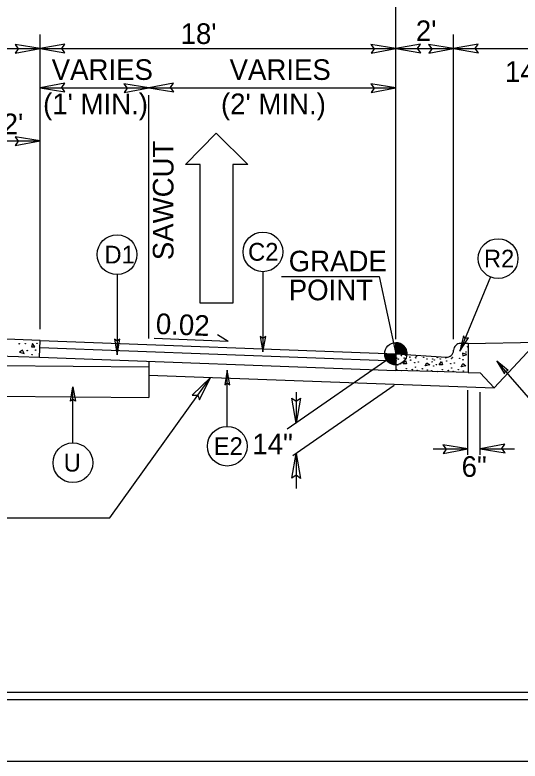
# Model space of a CAD drawing. Extents: x 573748 to 574632, y -54663 to -53209.
# Drawn here: x 574127.2 to 574163.9, y -54603.6 to -54549.4 of the extents above; entities that cross this region are included whole.
import ezdxf

# ---------------------------------------------------------------- set-up
doc = ezdxf.new("R2010")
doc.units = 0
for name, color, linetype in [('Prop Dimension', 7, 'Continuous'), ('Prop Dimension Text', 7, 'Continuous'), ('Prop Lane Arrow CELL', 7, 'Continuous'), ('Prop Terminator CELL', 7, 'Continuous'), ('Sheet Cutting Line CELL', 7, 'Continuous'), ('Sheet Plot Border Inside CELL', 7, 'Continuous'), ('Sheet Plot Border Outside CELL', 7, 'Continuous'), ('Sheet Typical CELL', 7, 'Continuous'), ('Typical Arrow Superelevation CELL', 7, 'Continuous'), ('Typical Curb CELL', 7, 'Continuous'), ('Typical Grade Point Symbol CELL', 7, 'Continuous'), ('Typical ID Circle CELL', 7, 'Continuous'), ('Typical Pavement Slope CELL', 7, 'Continuous'), ('Typical Terminator CELL', 7, 'Continuous'), ('Typical Text ID Circle CELL', 7, 'Continuous')]:
    doc.layers.add(name, color=color, linetype=linetype)

# ---------------------------------------------------------------- blocks, each defined once
blk = doc.blocks.new('Lane Arrow Through')
at = {"layer": 'Prop Lane Arrow CELL'}
for p, q in [((-3.15, 1.6), (-3.15, 3.1)), ((-3.15, 3.1), (0, 0)), ((-17.15, 1.6), (-3.15, 1.6)), ((-17.15, -1.7), (-17.15, 1.6)), ((0, 0), (-3.15, -3.2)), ((-3.15, -1.7), (-17.15, -1.7)), ((-3.15, -3.2), (-3.15, -1.7))]:
    blk.add_line(p, q, dxfattribs=at)

msp = doc.modelspace()

# ---------------------------------------------------------------- linework, layer by layer
at = {"layer": 'Prop Dimension'}
for p, q in [((574154.894, -54572.971), (574154.894, -54540.95)), ((574129.029, -54572.233), (574129.029, -54550.814)), ((574159.086, -54572.971), (574159.086, -54550.814)), ((574120.665, -54551.839), (574129.029, -54551.839)), ((574129.029, -54551.839), (574154.894, -54551.839)), ((574154.894, -54551.839), (574159.086, -54551.839)), ((574159.086, -54551.839), (574174.967, -54551.839)), ((574129.029, -54554.69), (574136.935, -54554.69)), ((574136.935, -54554.69), (574154.894, -54554.69)), ((574136.935, -54572.927), (574136.935, -54555.211)), ((574124.824, -54558.544), (574129.029, -54558.544)), ((574029.942, -54574.073), (574136.935, -54574.974)), ((574154.478, -54574.319), (574146.994, -54579.52)), ((574136.935, -54575.212), (574136.935, -54577.21)), ((574029.942, -54576.31), (574136.935, -54577.21)), ((574154.774, -54576.33), (574147.418, -54581.443)), ((574147.648, -54576.812), (574147.648, -54579.065)), ((574160.131, -54581.378), (574160.131, -54576.685)), ((574161.021, -54581.378), (574161.021, -54576.832)), ((574157.62, -54580.94), (574160.131, -54580.94)), ((574161.021, -54580.94), (574163.527, -54580.94)), ((574147.648, -54581.283), (574147.648, -54583.818))]:
    msp.add_line(p, q, dxfattribs=at)
for points in [[(574146.585, -54568.4), (574153.674, -54568.4), (574154.894, -54574.029)], [(574124.244, -54585.952), (574134.095, -54585.952), (574141.412, -54575.744)]]:
    msp.add_lwpolyline(points, dxfattribs=at)
at = {"layer": 'Prop Terminator CELL'}
for points in [[(574127.232, -54552.172), (574129.029, -54551.839), (574127.214, -54551.542), (574127.448, -54551.859)], [(574130.825, -54551.506), (574129.029, -54551.839), (574130.843, -54552.136), (574130.609, -54551.818)], [(574153.097, -54552.172), (574154.894, -54551.839), (574153.079, -54551.542), (574153.313, -54551.859)], [(574156.69, -54551.506), (574154.894, -54551.839), (574156.708, -54552.136), (574156.474, -54551.818)], [(574157.29, -54552.172), (574159.086, -54551.839), (574157.272, -54551.542), (574157.506, -54551.859)], [(574160.883, -54551.506), (574159.086, -54551.839), (574160.901, -54552.136), (574160.667, -54551.818)], [(574130.825, -54554.357), (574129.029, -54554.69), (574130.843, -54554.987), (574130.609, -54554.67)], [(574138.731, -54554.357), (574136.935, -54554.69), (574138.749, -54554.987), (574138.515, -54554.67)], [(574135.138, -54555.023), (574136.935, -54554.69), (574135.12, -54554.393), (574135.355, -54554.71)], [(574153.097, -54555.023), (574154.894, -54554.69), (574153.079, -54554.393), (574153.313, -54554.71)], [(574127.232, -54558.877), (574129.029, -54558.544), (574127.214, -54558.247), (574127.448, -54558.564)], [(574140.615, -54577.388), (574141.412, -54575.744), (574140.097, -54577.029), (574140.491, -54577.029)], [(574147.958, -54577.265), (574147.648, -54579.065), (574147.328, -54577.255), (574147.648, -54577.485)], [(574158.335, -54581.273), (574160.131, -54580.94), (574158.317, -54580.643), (574158.551, -54580.96)], [(574162.818, -54580.607), (574161.021, -54580.94), (574162.836, -54581.237), (574162.602, -54580.92)], [(574147.338, -54583.084), (574147.648, -54581.283), (574147.968, -54583.094), (574147.648, -54582.864)]]:
    msp.add_lwpolyline(points, close=True, dxfattribs=at)
at = {"layer": 'Sheet Cutting Line CELL'}
msp.add_line((573944.171, -54603.647), (574280.971, -54603.647), dxfattribs=at)
at = {"layer": 'Sheet Plot Border Inside CELL'}
msp.add_lwpolyline([(574280.071, -54388.137), (573946.771, -54388.137), (573946.771, -54599.157), (574280.071, -54599.157)], close=True, dxfattribs=at)
at = {"layer": 'Sheet Plot Border Outside CELL'}
msp.add_lwpolyline([(574280.971, -54383.647), (573944.171, -54383.647), (573944.171, -54603.647), (574280.971, -54603.647)], close=True, dxfattribs=at)
at = {"layer": 'Sheet Typical CELL'}
msp.add_lwpolyline([(574277.571, -54388.647), (573977.571, -54388.647), (573977.571, -54598.647), (574277.571, -54598.647)], close=True, dxfattribs=at)
at = {"layer": 'Typical Arrow Superelevation CELL'}
for q in [(574141.936, -54572.652), (574137.319, -54572.918)]:
    msp.add_line((574142.709, -54573.142), q, dxfattribs=at)
at = {"layer": 'Typical Curb CELL'}
for p, q in [((574129.029, -54573.062), (574124.824, -54572.904)), ((574128.484, -54573.276), (574128.403, -54573.512)), ((574128.656, -54573.535), (574128.484, -54573.276)), ((574128.984, -54574.286), (574129.029, -54573.062)), ((574160.154, -54573.292), (574159.608, -54573.278)), ((574127.762, -54573.762), (574127.54, -54573.911)), ((574127.884, -54574.007), (574127.762, -54573.762)), ((574128.403, -54573.512), (574128.656, -54573.535)), ((574159.093, -54573.789), (574159.093, -54573.766)), ((574120.588, -54573.979), (574128.984, -54574.286)), ((574127.54, -54573.911), (574127.884, -54574.007)), ((574154.894, -54574.029), (574158.557, -54574.277)), ((574159.736, -54573.98), (574159.766, -54574.17)), ((574160.057, -54574.082), (574159.736, -54573.98)), ((574159.766, -54574.17), (574160.057, -54574.082)), ((574155.421, -54574.763), (574155.608, -54574.517)), ((574155.674, -54574.757), (574155.421, -54574.763)), ((574155.608, -54574.517), (574155.674, -54574.757)), ((574157.022, -54574.912), (574157.159, -54574.675)), ((574157.371, -54574.838), (574157.022, -54574.912)), ((574157.159, -54574.675), (574157.371, -54574.838)), ((574158.039, -54574.831), (574158.225, -54574.585)), ((574158.291, -54574.825), (574158.039, -54574.831)), ((574158.225, -54574.585), (574158.291, -54574.825)), ((574159.638, -54574.979), (574159.776, -54574.743)), ((574159.987, -54574.906), (574159.638, -54574.979)), ((574159.776, -54574.743), (574159.987, -54574.906)), ((574160.154, -54575.388), (574154.894, -54575.252))]:
    msp.add_line(p, q, dxfattribs=at)
for centre in [(574127.516, -54573.302), (574127.964, -54573.298), (574128.811, -54573.268), (574128.099, -54573.793), (574128.712, -54573.764), (574159.667, -54573.438), (574160.002, -54573.901), (574160.12, -54573.522), (574128.455, -54574.091), (574154.956, -54574.344), (574155.072, -54574.418), (574155.306, -54574.163), (574155.504, -54574.346), (574155.606, -54574.135), (574155.913, -54574.275), (574156.343, -54574.319), (574156.381, -54574.215), (574156.918, -54574.288), (574157.167, -54574.401), (574157.573, -54574.411), (574157.921, -54574.295), (574158.121, -54574.414), (574158.531, -54574.342), (574158.96, -54574.387), (574158.999, -54574.282), (574159.535, -54574.356), (574154.915, -54574.546), (574155.027, -54574.848), (574155.231, -54574.758), (574155.968, -54574.489), (574156.274, -54574.677), (574156.539, -54574.624), (574157.532, -54574.614), (574157.644, -54574.916), (574157.689, -54574.486), (574157.848, -54574.825), (574158.585, -54574.557), (574158.891, -54574.745), (574159.156, -54574.692), (574159.784, -54574.468), (574154.948, -54575.181), (574155.326, -54575.251), (574155.664, -54575.116), (574156.093, -54575.175), (574156.337, -54575.002), (574156.451, -54575.244), (574156.825, -54575.122), (574157.181, -54575.215), (574157.503, -54575.259), (574157.943, -54575.318), (574158.281, -54575.184), (574158.71, -54575.243), (574158.954, -54575.069), (574159.068, -54575.312), (574159.442, -54575.19), (574159.799, -54575.283)]:
    msp.add_circle(centre, 0.0168, dxfattribs=at)
for centre, start, end in [((574159.595, -54573.779), 88.5196, 178.5196), ((574158.591, -54573.776), 266.1351, 358.5196)]:
    msp.add_arc(centre, 0.502, start, end, dxfattribs=at)
at = {"layer": 'Typical Grade Point Symbol CELL'}
for p, q in [((574154.894, -54574.029), (574154.894, -54573.224)), ((574154.088, -54574.029), (574154.894, -54574.029)), ((574154.892, -54574.835), (574154.894, -54574.029)), ((574154.894, -54574.029), (574154.892, -54574.835)), ((574155.699, -54574.029), (574154.894, -54574.029))]:
    msp.add_line(p, q, dxfattribs=at)
for points in [[(574154.901, -54573.224), (574154.901, -54573.224), (574154.901, -54574.029)], [(574154.917, -54573.224), (574154.917, -54574.029)], [(574154.933, -54573.225), (574154.933, -54574.029)], [(574154.949, -54573.225), (574154.949, -54574.029)], [(574154.965, -54573.227), (574154.965, -54574.029)], [(574154.981, -54573.229), (574154.981, -54574.029)], [(574154.998, -54573.231), (574154.998, -54574.029)], [(574155.014, -54573.232), (574155.014, -54574.029)], [(574155.03, -54573.234), (574155.03, -54574.029)], [(574155.046, -54573.238), (574155.046, -54574.029)], [(574155.062, -54573.241), (574155.062, -54574.029)], [(574155.078, -54573.245), (574155.078, -54574.029)], [(574155.094, -54573.249), (574155.094, -54574.029)], [(574155.11, -54573.254), (574155.11, -54574.029)], [(574155.126, -54573.258), (574155.126, -54574.029)], [(574155.143, -54573.263), (574155.143, -54574.029)], [(574155.159, -54573.268), (574155.159, -54574.029)], [(574155.175, -54573.274), (574155.175, -54574.029)], [(574155.191, -54573.281), (574155.191, -54574.029)], [(574155.207, -54573.288), (574155.207, -54574.029)], [(574155.223, -54573.295), (574155.223, -54574.029)], [(574155.239, -54573.302), (574155.239, -54574.029)], [(574155.255, -54573.309), (574155.255, -54574.029)], [(574155.272, -54573.318), (574155.272, -54574.029)], [(574155.288, -54573.327), (574155.288, -54574.029)], [(574155.304, -54573.336), (574155.304, -54574.029)], [(574155.32, -54573.345), (574155.32, -54574.029)], [(574155.336, -54573.356), (574155.336, -54574.029)], [(574155.352, -54573.367), (574155.352, -54574.029)], [(574155.368, -54573.379), (574155.368, -54574.029)], [(574155.384, -54573.39), (574155.384, -54574.029)], [(574155.4, -54573.403), (574155.4, -54574.029)], [(574155.417, -54573.417), (574155.417, -54574.029)], [(574155.433, -54573.431), (574155.433, -54574.029)], [(574155.449, -54573.446), (574155.449, -54574.029)], [(574155.465, -54573.462), (574155.465, -54574.029)], [(574155.481, -54573.478), (574155.481, -54574.029)], [(574155.497, -54573.496), (574155.497, -54574.029)], [(574155.513, -54573.515), (574155.513, -54574.029)], [(574155.529, -54573.535), (574155.529, -54574.029)], [(574155.545, -54573.557), (574155.545, -54574.029)], [(574155.562, -54573.58), (574155.562, -54574.029)], [(574155.578, -54573.605), (574155.578, -54574.029)], [(574155.594, -54573.632), (574155.594, -54574.029)], [(574155.61, -54573.66), (574155.61, -54574.029)], [(574155.626, -54573.694), (574155.626, -54574.029)], [(574155.642, -54573.732), (574155.642, -54574.029)], [(574155.658, -54573.777), (574155.658, -54574.029)], [(574155.674, -54573.832), (574155.674, -54574.029)], [(574154.092, -54574.029), (574154.092, -54574.117)], [(574154.108, -54574.029), (574154.108, -54574.212)], [(574154.124, -54574.029), (574154.124, -54574.269)], [(574154.14, -54574.029), (574154.14, -54574.317)], [(574154.156, -54574.029), (574154.156, -54574.355)], [(574154.172, -54574.029), (574154.172, -54574.389)], [(574154.188, -54574.029), (574154.188, -54574.419)], [(574154.205, -54574.029), (574154.205, -54574.448)], [(574154.221, -54574.029), (574154.221, -54574.473)], [(574154.237, -54574.029), (574154.237, -54574.497)], [(574154.253, -54574.029), (574154.253, -54574.518)], [(574154.269, -54574.029), (574154.269, -54574.538)], [(574154.285, -54574.029), (574154.285, -54574.557)], [(574154.301, -54574.029), (574154.301, -54574.575)], [(574154.317, -54574.029), (574154.317, -54574.593)], [(574154.333, -54574.029), (574154.333, -54574.609)], [(574154.35, -54574.029), (574154.35, -54574.624)], [(574154.366, -54574.029), (574154.366, -54574.638)], [(574154.382, -54574.029), (574154.382, -54574.652)], [(574154.398, -54574.029), (574154.398, -54574.665)], [(574154.414, -54574.029), (574154.414, -54574.677)], [(574154.43, -54574.029), (574154.43, -54574.688)], [(574154.446, -54574.029), (574154.446, -54574.699)], [(574154.462, -54574.029), (574154.462, -54574.71)], [(574154.478, -54574.029), (574154.478, -54574.72)], [(574154.495, -54574.029), (574154.495, -54574.729)], [(574154.511, -54574.029), (574154.511, -54574.738)], [(574154.527, -54574.029), (574154.527, -54574.747)], [(574154.543, -54574.029), (574154.543, -54574.754)], [(574154.559, -54574.029), (574154.559, -54574.762)], [(574154.575, -54574.029), (574154.575, -54574.769)], [(574154.591, -54574.029), (574154.591, -54574.776)], [(574154.607, -54574.029), (574154.607, -54574.783)], [(574154.623, -54574.029), (574154.623, -54574.788)], [(574154.64, -54574.029), (574154.64, -54574.794)], [(574154.656, -54574.029), (574154.656, -54574.799)], [(574154.672, -54574.029), (574154.672, -54574.803)], [(574154.688, -54574.029), (574154.688, -54574.808)], [(574154.704, -54574.029), (574154.704, -54574.812)], [(574154.72, -54574.029), (574154.72, -54574.815)], [(574154.736, -54574.029), (574154.736, -54574.819)], [(574154.752, -54574.029), (574154.752, -54574.822)], [(574154.768, -54574.029), (574154.768, -54574.824)], [(574154.785, -54574.029), (574154.785, -54574.828)], [(574154.801, -54574.029), (574154.801, -54574.829)], [(574154.817, -54574.029), (574154.817, -54574.831)], [(574154.833, -54574.029), (574154.833, -54574.833)], [(574154.849, -54574.029), (574154.849, -54574.833)], [(574154.865, -54574.029), (574154.865, -54574.835)], [(574154.881, -54574.029), (574154.881, -54574.835), (574154.881, -54574.835)], [(574155.69, -54573.915), (574155.69, -54574.029)]]:
    msp.add_lwpolyline(points, dxfattribs=at)
msp.add_circle((574154.893, -54574.029), 0.806, dxfattribs=at)
for start, end in [(359.9905, 89.9905), (179.9905, 269.9905)]:
    msp.add_arc((574154.893, -54574.029), 0.806, start, end, dxfattribs=at)
at = {"layer": 'Typical ID Circle CELL'}
for p, q in [((574134.627, -54568.263), (574134.627, -54574.097)), ((574145.236, -54568.06), (574145.236, -54573.894)), ((574161.778, -54568.442), (574159.556, -54573.836)), ((574165.552, -54578.381), (574162.246, -54574.56)), ((574142.641, -54579.306), (574142.641, -54575.223)), ((574131.421, -54580.508), (574131.421, -54576.425))]:
    msp.add_line(p, q, dxfattribs=at)
for centre in [(574145.236, -54566.617), (574134.626, -54566.82), (574162.327, -54567.108), (574142.641, -54580.749), (574131.421, -54581.951)]:
    msp.add_circle(centre, 1.443, dxfattribs=at)
at = {"layer": 'Typical Pavement Slope CELL'}
for p, q in [((574129.029, -54573.062), (574154.894, -54574.029)), ((574160.154, -54573.292), (574174.965, -54572.969)), ((574160.154, -54573.292), (574160.154, -54575.388)), ((574162.049, -54576.514), (574165.154, -54573.183)), ((574129.01, -54573.575), (574154.894, -54574.543)), ((574128.984, -54574.286), (574154.894, -54575.252)), ((574154.894, -54574.029), (574154.894, -54575.252)), ((574136.935, -54574.582), (574136.935, -54575.577)), ((574160.154, -54575.388), (574161.035, -54575.426)), ((574162.049, -54576.514), (574161.035, -54575.426)), ((574136.935, -54575.577), (574162.049, -54576.514))]:
    msp.add_line(p, q, dxfattribs=at)
at = {"layer": 'Typical Terminator CELL'}
for points in [[(574145.042, -54572.769), (574145.236, -54573.894), (574145.436, -54572.763), (574145.236, -54572.907)], [(574159.806, -54572.722), (574159.556, -54573.836), (574160.172, -54572.866), (574159.932, -54572.923)], [(574134.433, -54572.972), (574134.627, -54574.097), (574134.827, -54572.966), (574134.627, -54573.109)], [(574163.073, -54575.238), (574162.246, -54574.56), (574162.798, -54575.484), (574162.852, -54575.26)], [(574142.822, -54576.277), (574142.641, -54575.223), (574142.453, -54576.283), (574142.641, -54576.148)], [(574131.239, -54577.479), (574131.421, -54576.425), (574131.608, -54577.485), (574131.421, -54577.35)]]:
    msp.add_lwpolyline(points, close=True, dxfattribs=at)

# ---------------------------------------------------------------- block references
at = {"layer": 'Prop Dimension Text', "xscale": 0.7200000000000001, "yscale": 0.7200000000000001, "rotation": 90.00000000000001}
msp.add_blockref('Lane Arrow Through', (574141.831, -54557.993), dxfattribs=at)

# ---------------------------------------------------------------- texts
at = {"layer": 'Prop Dimension Text'}
for s, p in [("18'", (574139.249, -54551.5)), ("2'", (574156.352, -54551.289)), ('VARIES', (574129.878, -54554.113)), ('VARIES', (574142.811, -54554.113)), ("14' W/ GR", (574162.827, -54554.256)), ("(1' MIN.)", (574129.252, -54556.605)), ("(2' MIN.)", (574142.184, -54556.605)), ("2'", (574126.314, -54558.059)), ('GRADE', (574147.109, -54568.037)), ('POINT', (574147.109, -54570.137)), ('14"', (574144.467, -54581.343)), ('6"', (574159.679, -54582.978))]:
    msp.add_text(s, height=1.5, dxfattribs=at).set_placement(p)
for s, rotation, p in [('SAWCUT', 90, (574138.732, -54567.221)), ('0.02', 357.6243, (574137.425, -54572.58))]:
    msp.add_text(s, height=1.5, rotation=rotation, dxfattribs=at).set_placement(p)
at = {"layer": 'Typical Text ID Circle CELL'}
for s, height, p in [('D1', 1.2912, (574133.71, -54567.463)), ('C2', 1.2912, (574144.154, -54567.26)), ('R2', 1.2912, (574161.3, -54567.754)), ('E2', 1.2912, (574141.659, -54581.392)), ('U', 1.291, (574130.75, -54582.594))]:
    msp.add_text(s, height=height, dxfattribs=at).set_placement(p)

doc.saveas('drawing.dxf')
